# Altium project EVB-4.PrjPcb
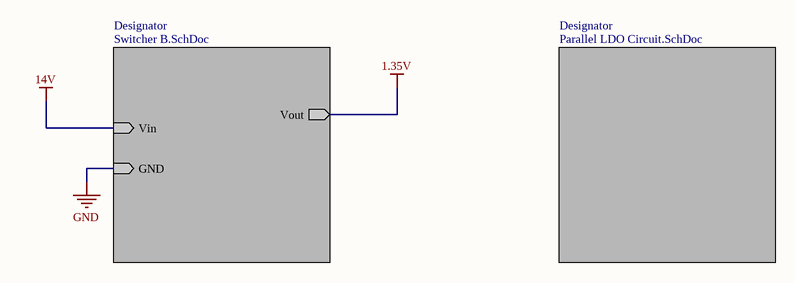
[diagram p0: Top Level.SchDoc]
Engineer: "Engineer"; Project: "Project"
3 sheets, 34 parts. Net scope: hierarchical (ports join the sheet entries above them; power ports are global).
Sheets:
  Top Level.SchDoc
    Designator = Switcher B.SchDoc
    Designator = Parallel LDO Circuit.SchDoc

## Sheet Top Level.SchDoc
size 431 x 279 mm; Organization: UTVATE; Address1: ADDRESS 1; Address2: ADDRESS 2; Address3: ADDRESS 3; Address4: ADDRESS 4; Revision: -; SheetNumber: 1; SheetTotal: 3; Project: EVB-4.PrjPcb; ENG_APP_DATE: YYYY/MM/DD; DSN_APP_DATE: YYYY/MM/DD; CHK_APP_DATE: YYYY/MM/DD

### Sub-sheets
Designator = Switcher B.SchDoc: Vout (out), Vin (in), GND (in)
Designator = Parallel LDO Circuit.SchDoc: no entries

## Sheet Switcher B.SchDoc
size 431 x 279 mm; Organization: UTVATE; Address1: ADDRESS 1; Address2: ADDRESS 2; Address3: ADDRESS 3; Address4: ADDRESS 4; Revision: -; SheetNumber: 2; SheetTotal: 3; Project: EVB-4.PrjPcb; ENG_APP_DATE: YYYY/MM/DD; DSN_APP_DATE: YYYY/MM/DD; CHK_APP_DATE: YYYY/MM/DD
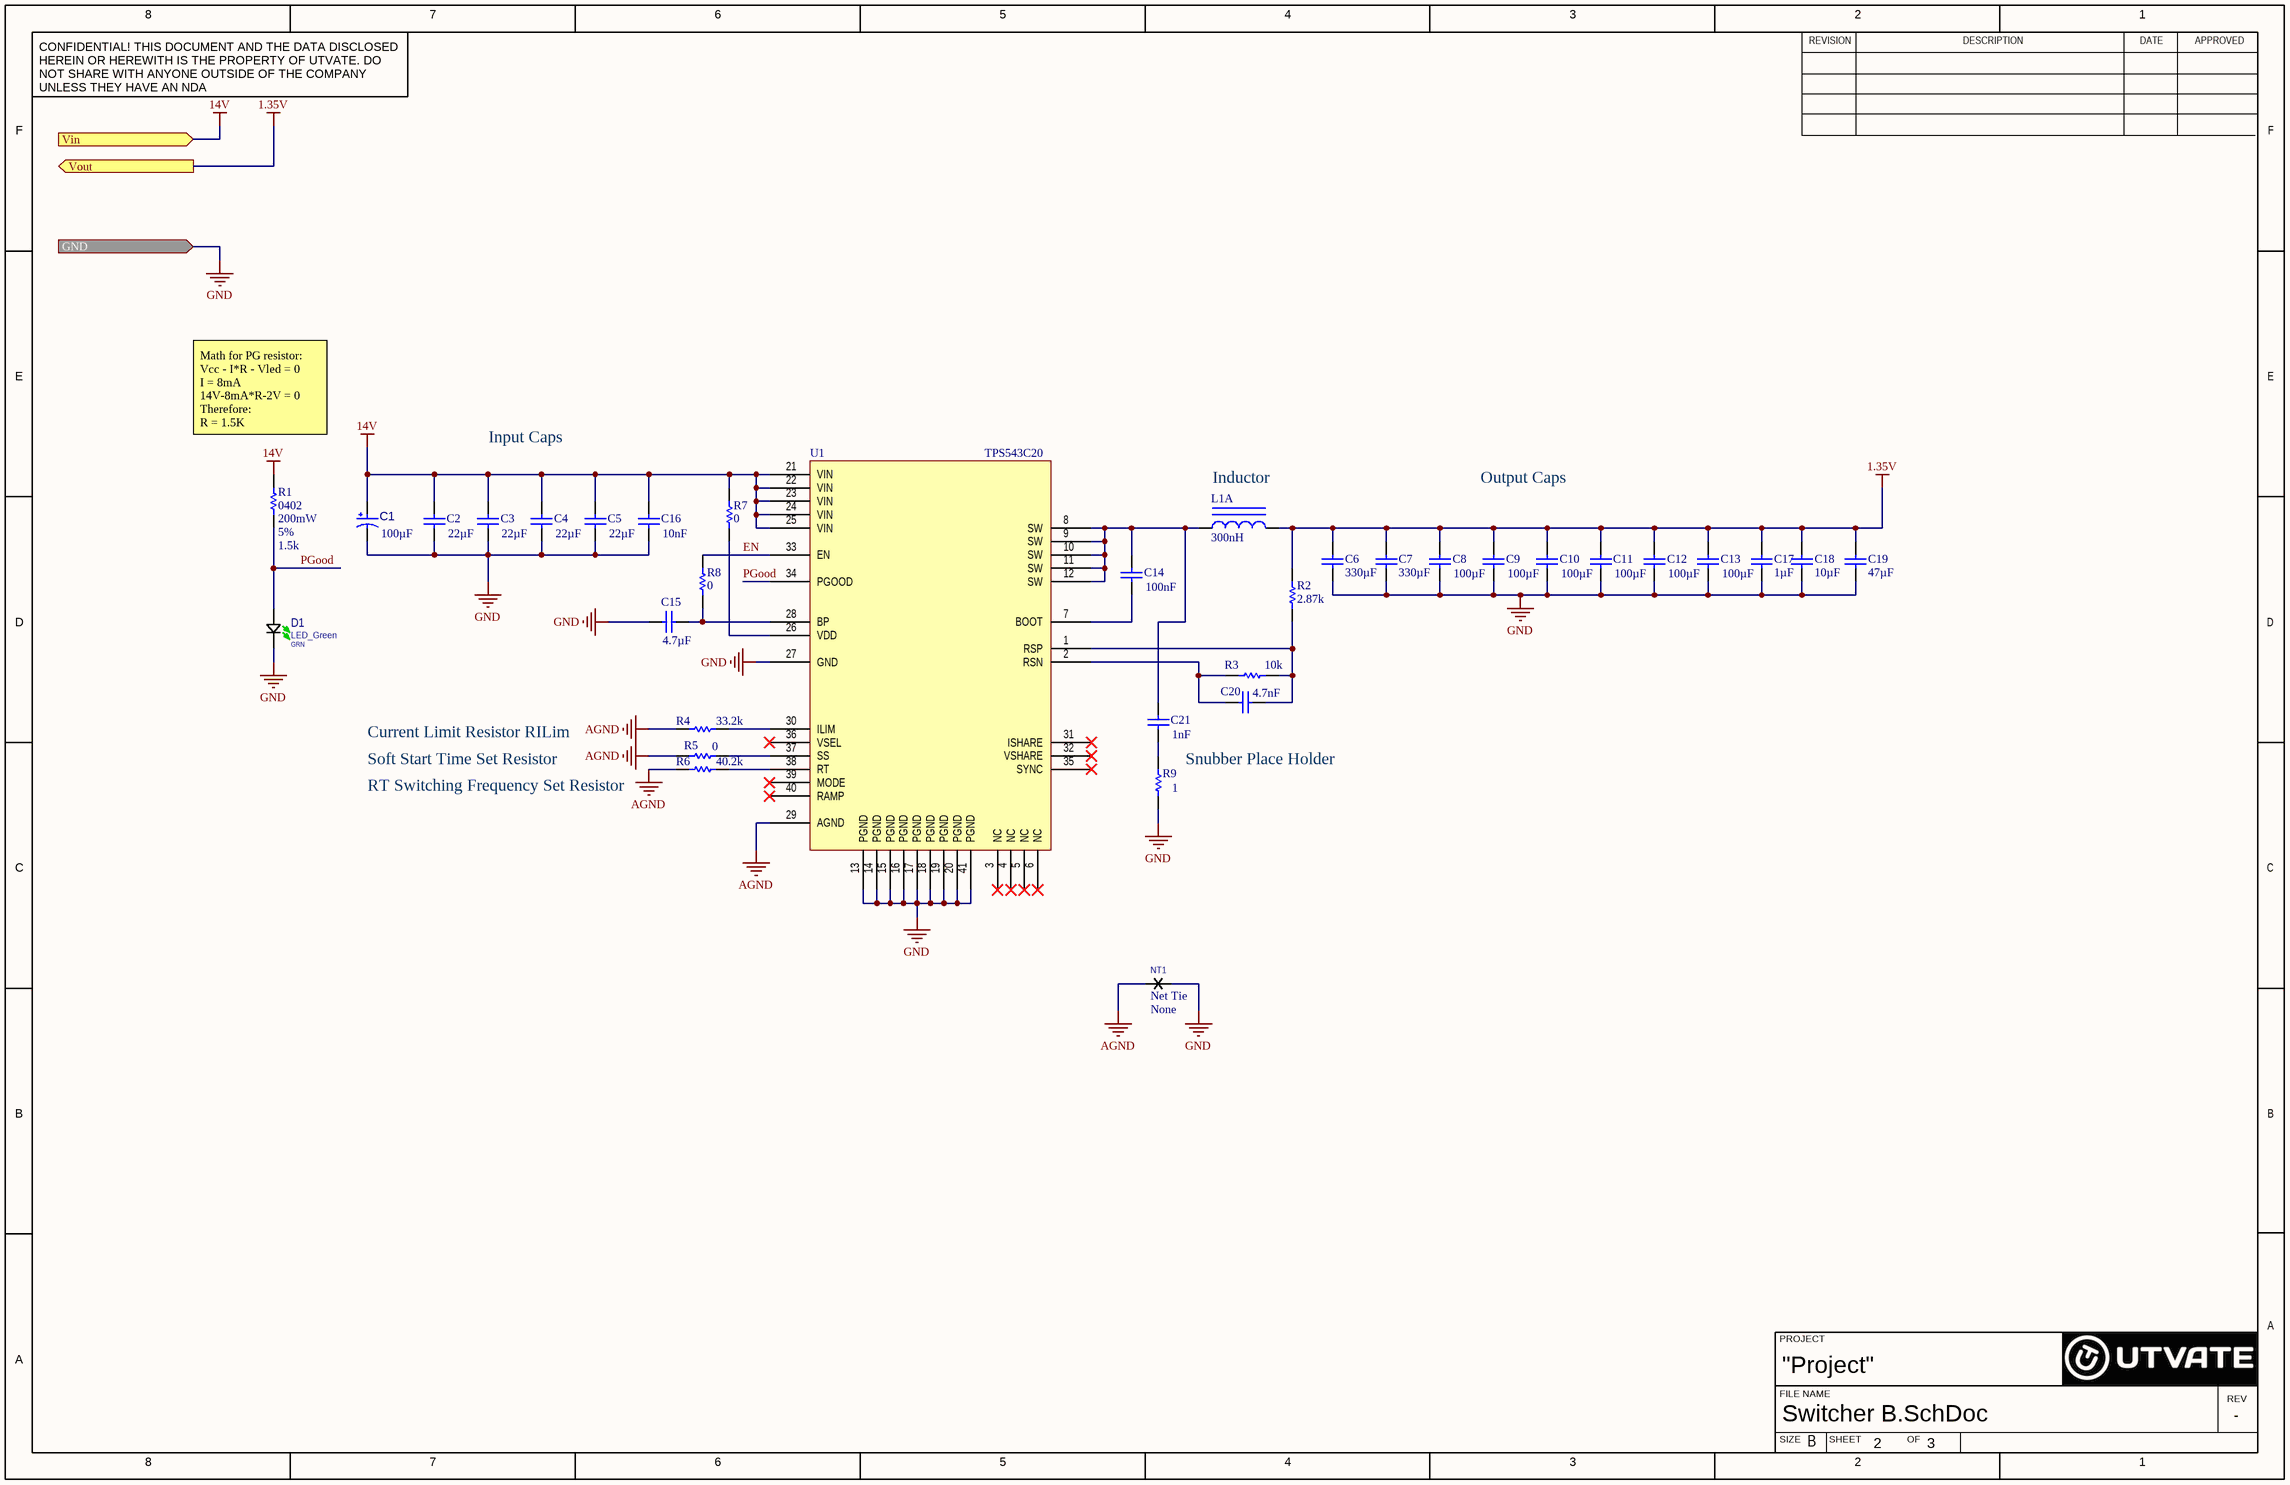
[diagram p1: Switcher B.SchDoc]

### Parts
C1  value 100µF  [CAPMP7344X31-T_V]  (hidden comment: TAJE107M025SNJV)
C2  value 22µF  [CAP_1210_Most]  (hidden comment: CL32B226KAJNNNE)
C3  value 22µF  [CAP_1210_Most]  (hidden comment: CL32B226KAJNNNE)
C4  value 22µF  [CAP_1210_Most]  (hidden comment: CL32B226KAJNNNE)
C5  value 22µF  [CAP_1210_Most]  (hidden comment: CL32B226KAJNNNE)
C6  value 330µF  [CAP_1210_Most]  (hidden comment: GRM32ER60G337ME05L)
C7  value 330µF  [CAP_1210_Most]  (hidden comment: GRM32ER60G337ME05L)
C8  value 100µF  [CAP_0805_Nominal]  (hidden comment: GRM21BR60J107ME15K)
C9  value 100µF  [CAP_0805_Nominal]  (hidden comment: GRM21BR60J107ME15K)
C10  value 100µF  [CAP_0805_Nominal]  (hidden comment: GRM21BR60J107ME15K)
C11  value 100µF  [CAP_0805_Nominal]  (hidden comment: GRM21BR60J107ME15K)
C12  value 100µF  [CAP_0805_Nominal]  (hidden comment: GRM21BR60J107ME15K)
C13  value 100µF  [CAP_0805_Nominal]  (hidden comment: GRM21BR60J107ME15K)
C14  value 100nF  [CAP_0603_Nominal]  (hidden comment: 100nF 0603 Capcaitor)
C15  value 4.7µF  [CAP_0603_Nominal]  (hidden comment: C1608X5R1E475K080AC)
C16  value 10nF  [CAP_0402_Nominal]  (hidden comment: C0402C103K4RECAUTO)
C17  value 1µF  [CAP_0402_Nominal]  (hidden comment: 0402ZD105KAT2A)
C18  value 10µF  [CAP_0402_Nominal]  (hidden comment: GRM155R60J106ME15D)
C19  value 47µF  [CAP_0603_Nominal]  (hidden comment: GRM188R60J476ME15D)
C20  value 4.7nF  [CAP_0402_Nominal]  (hidden comment: 0402YC472KAT2A)
C21  value 1nF  [CAP_0603_Nominal]  (hidden comment: KAM15AR71H102KT)
D1  LED_Green  Color: GRN  [DIOC1608X06N]
L1  value 300nH  [COIL-SER2009-3_V]  (hidden comment: 300nH Inductor)  (part A of 2)
NT1  Net Tie  Manufacturer: None  [Net Tie-Footprint-1]  (net tie, no BOM)
R1  value 1.5k  Case/Package: 0402  Power: 200mW  Tolerance: 5%  [RES_0402_Most]  (hidden comment: RCS04021K50JNED)
R2  value 2.87k  [RES_0402_Nominal]  (hidden comment: Res 2.87k 0402)
R3  value 10k  [RES_0402_Most]  (hidden comment: ERJ-2RKF1002X)
R4  value 33.2k  [RES_0402_Most]  (hidden comment: CRCW040233K2FKED)
R5  value 0  [RES_0402_Most]  (hidden comment: RC0402JR-070RL)
R6  value 40.2k  [RES_0402_Nominal]  (hidden comment: Res 40.2K 0402)
R7  value 0  [RES_0402_Most]  (hidden comment: RC0402JR-070RL)
R8  value 0  [RES_0402_Most]  (hidden comment: RC0402JR-070RL)
R9  value 1  [RES_0805_Nominal]  (hidden comment: CRCW08051R00FKEAHP)
U1  TPS543C20  [TPS543C20 -Footprint-1]

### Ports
GND (in), Vin (in), Vout (out)

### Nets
1.35V: C6.2 C7.2 C8.2 C9.2 C10.2 C11.2 C12.2 C13.2 C17.2 C18.2 C19.2 L1.2 R2.2 ; port Vout
14V: C1.1 C2.2 C3.2 C4.2 C5.2 C16.2 R1.2 R7.1 U1.21(VIN) U1.22(VIN) U1.23(VIN) U1.24(VIN) U1.25(VIN) ; port Vin
AGND: NT1.1 R4.1 R5.1 R6.1 U1.29(AGND)
GND: C1.2 C2.1 C3.1 C4.1 C5.1 C6.1 C7.1 C8.1 C9.1 C10.1 C11.1 C12.1 C13.1 C15.1 C16.1 C17.1 C18.1 C19.1 D1.1 NT1.2 R9.1 U1.13(PGND) U1.14(PGND) U1.15(PGND) U1.16(PGND) U1.17(PGND) U1.18(PGND) U1.19(PGND) U1.20(PGND) U1.27(GND) U1.41(PGND) ; port GND
EN: R8.1 U1.33(EN)
PGood: D1.2 R1.1 U1.34(PGOOD)
NetC14_1: C14.1 U1.7(BOOT)
NetC14_2: C14.2 C21.2 L1.1 U1.8(SW) U1.9(SW) U1.10(SW) U1.11(SW) U1.12(SW)
NetC15_2: C15.2 R8.2 U1.28(BP)
NetC20_1: C20.1 R2.1 R3.1 U1.1(RSP)
NetC20_2: C20.2 R3.2 U1.2(RSN)
NetC21_1: C21.1 R9.2
NetR4_2: R4.2 U1.30(ILIM)
NetR5_2: R5.2 U1.37(SS)
NetR6_2: R6.2 U1.38(RT)
NetR7_2: R7.2 U1.26(VDD)

Not connected (* = marked no-connect by the designer): U1 3(NC)* 4(NC)* 5(NC)* 6(NC)* 31(ISHARE)* 32(VSHARE)* 35(SYNC)* 36(VSEL)* 39(MODE)* 40(RAMP)*

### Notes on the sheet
- Math for PG resistor:
  Vcc - I*R - Vled = 0
  I = 8mA
  14V-8mA*R-2V = 0
  Therefore:
  R = 1.5K
- Input Caps
- Input Capacitance target was > 50uF effective ceramic capacitor capacitance , this is achieved with 4 22uF Low ESR 25V rated capacitors and one 25V 100uF tantalum capacitor placed in parallel to VIN pins.
  Update 10nF cap to 25v rated RF cap. Tps543c20 datasheet recommends 2.2nF 0603 RF caps. Maybe TI could provide PN.
- (near L1) Inductor
- Output Caps
- Inductor Selection:
  Datasheet: https://www.coilcraft.com/getmedia/56db8f04-6d7a-4e93-ad3f-acf7c2a14b74/ser2000.pdf
  IMax  100A > 2x 29A(max operating current)
  ISat 54A > 1.5X29A  (max operating current)
  SFR Chosen > decade higher switching frequency(500KHz)
  300nH to meet goal 320nH from TI TPS543C20 Design Calculator E equation.( Gives optimized choice for meeting operating needs and switching current ripple at 500KHz)
- Output Capacitance:
  ~
  300uF output capacitance which reduces output ripple but avoids introducing loop instability.
  2x330uF caps utilized to decrease footprint.
- Current Limit Resistor RILim
- Soft Start Time Set Resistor
- Snubber Place Holder
- RILim chosen to set current limit at 35A. This can be reduced once we have verified 25.5A max operating current.
- Rss set at 0 ohms sets the soft start to 500 nS
- RT Switching Frequency Set Resistor
- (near R2) RFB Top set at 2.87K
  RFB Bottom set at 10K
  Sets output voltage ~ 1.35V
- (near R6) Rt chosen to set switching frequency at 500KHz
  500KHz is TI's recommended switching frequency for TPS543C20 for applications trying to achieve the parts maximum efficiency.

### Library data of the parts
C1 = CMP-001-00023-6: Cap Pol 100uF 2917 25V; Manufacturer: Kyocera AVX; Tolerance: 20%; Capacitor Type: Tantalum
C2-C5 = CMP-001-00028-14: Cap 22uF 1210 25V; Manufacturer: Samsung; Dielectric: X7R; Tolerance: 10%; Capacitor Type: Ceramic
C6 C7 = CMP-001-00015-15: Cap 330uF 1210 4V; Manufacturer: Murata; Capacitor Type: Ceramic; Tolerance: 20%; Dielectric: X5R
C8-C13 = CMP-001-00022-9: Cap 100uF 0805 6.3V; Manufacturer: Murata; Tolerance: 20%; Dielectric: X5R; Capacitor Type: Ceramic
C14 = CMP-001-00047-1: 100nF 0603 50V; Manufacturer Part Number: 06035D104KAT4A; Manufacturer: Kyocera AVX; Tolerance: 10%; Capacitor Type: Ceramic
C15 = CMP-001-00017-4: Cap 4.7uF 0603 25V; Manufacturer: TDK; Tolerance: 10%; Capacitor Type: Ceramic; Dielectric: X5R
C16 = CMP-001-00083-18: RF Cap 10nF 0402; Manufacturer: KEMET; Dielectric: X7R; Capacitor Type: Ceramic; Tolerance: 10%; Voltage Rating: 16V
C17 = CMP-001-00009-19: Cap 1uF 0402 10V; Manufacturer: Kyocera Avx; Capacitor Type: Ceramic; Tolerance: 10%; Dielectric: X5R
C18 = CMP-001-00074-19: Cap 10uF 0402 6.3V; Manufacturer: Murata; Tolerance: 20%; Capacitor Type: Ceramic; Dielectric: X5R
C19 = CMP-001-00048-1: CAP CER 47UF 6.3V X5R 0603; Manufacturer: Murata; Tolerance: 20%; Capacitor Type: Ceramic
C20 = CMP-001-00020-12: Cap 4.7nF 0402 16V; Manufacturer: Kyocera Avx; Dielectric: X7R; Capacitor Type: Ceramic; Tolerance: 10%
C21 = CMP-001-00049-1: Multilayer Ceramic Capacitors MLCC - SMD/SMT 50V 1000pF X7R 0603 10% AEC-Q200; Manufacturer: Kyocera AVX
D1 = CMP-011-0002-6: LED, GREEN, 0603, 2V; Manufacturer: Lite-On Inc.; Manufacturer Part Number: LTST-C191KGKT; Forward Current: 20mA
L1 = CMP-006-00014-1: General Purpose Inductor, 0.3uH, 20%, 1 Element, Ferrite-Core, SMD, 7636; Manufacturer Part Number: SER2009-301MLD; Manufacturer: CoilCraft; Case/Size Code: 7674; Inductor Application: POWER INDUCTOR; Package Width: 18.7mm; Max Current Rating: 100A; Package Length: 19.18mm; Shielding: Unshielded; Shape/Size Description: RECTANGULAR PACKAGE; Self Resonant Frequency: 550MHz; Package Height: 8.64mm; Channels: 1; Max Current: 54A; Test Frequency: 100kHz; DC Resistance (DCR): 0.74mR
NT1 = CMP-006-0011-2: All Copper net tie to join two nets together in a specific location
R1 = CMP-009-00072-5: Res 1.5k 0402; Manufacturer: Vishay Dale; Voltage Rating: 50V; Temperature Coefficient: 200ppm/°C
R2 = CMP-009-00083-1: RES 2.87K OHM 1% 1/16W 0402; Manufacturer Part Number: RC0402FR-072K87L; Manufacturer: Yageo; Power: 63mW
R3 = CMP-009-00012-12: Res 10k 0402; Manufacturer: Panasonic; Temperature Coefficient: 100ppm/°C; Tolerance: 1%; Power: 100mW; Voltage Rating: 50V
R4 = CMP-009-00011-12: Res 33.2k 0402; Manufacturer: Vishay Dale; Temperature Coefficient: 100ppm/°C; Power: 63mW; Tolerance: 1%; Voltage Rating: 50V
R5 R7 R8 = CMP-009-00004-16: Res 0R 0402; Manufacturer: Yageo; Voltage Rating: 50V; Power: 63mW; Tolerance: 1%
R6 = CMP-009-00082-1: 40.2K 0402; Manufacturer Part Number: RCS040240K2FKED; Manufacturer: Vishay Dale; Power: 200mW; Tolerance: 1%
R9 = CMP-009-00084-1: RES SMD 1 OHM 1% 1/2W 0805; Manufacturer: Vishay Dale; Power: 500mW
U1 = CMP-019-00006-1: Switching Regulator, Current-mode, 40A, 2000kHz Switching Freq-Max, PQCC40; Manufacturer: Texas Instruments; Min Supply Voltage: 4V; Output Voltage: 5.5V; Max Supply Voltage: 16V

## Sheet Parallel LDO Circuit.SchDoc
size 431 x 279 mm; Organization: UTVATE; Address1: ADDRESS 1; Address2: ADDRESS 2; Address3: ADDRESS 3; Address4: ADDRESS 4; Revision: -; SheetNumber: 2; SheetTotal: 2; Project: EVB-4.PrjPcb; ENG_APP_DATE: YYYY/MM/DD; DSN_APP_DATE: YYYY/MM/DD; CHK_APP_DATE: YYYY/MM/DD

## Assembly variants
Standard: all parts fitted
Variant of EVB-4: not fitted C21 R9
